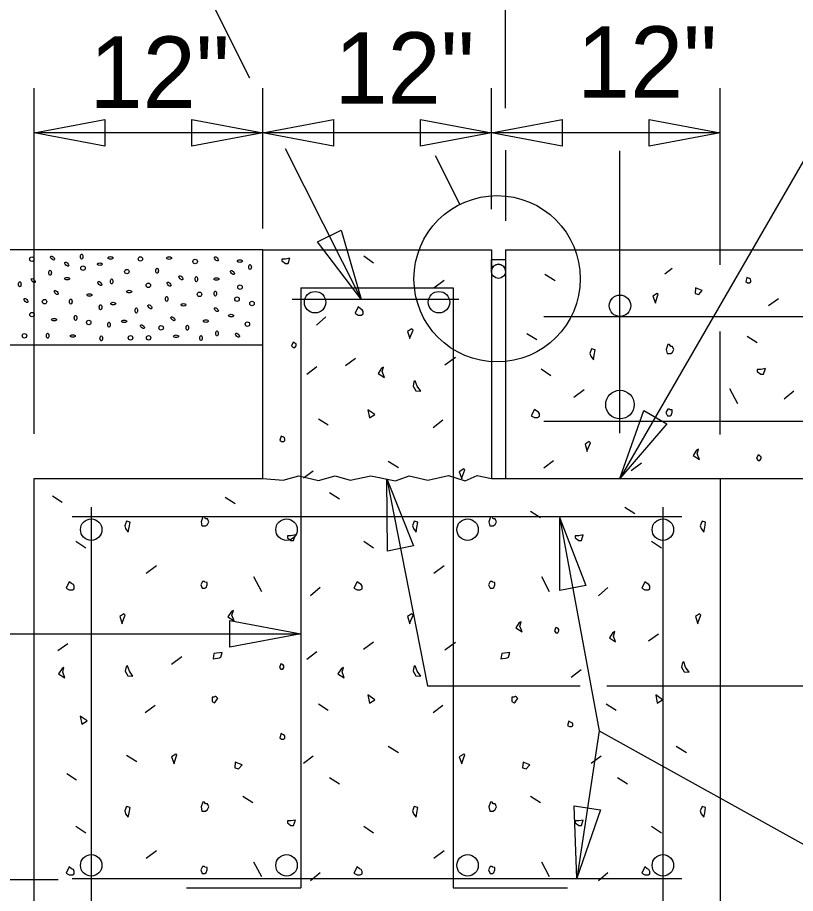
# Model space of a CAD drawing. Extents: x 0 to 68.6, y 0 to 47.1.
# Drawn here: x 29.508 to 32.911, y 9.542 to 13.374 of the extents above; entities that cross this region are included whole.
import ezdxf

# ---------------------------------------------------------------- set-up
doc = ezdxf.new("R2010")
doc.units = 0
for name, color, linetype in [('BRDG_ANNO_General-Notes', 7, 'Continuous'), ('BRDG_BASE_Dtlctrln', 7, 'Continuous'), ('BRDG_BASE_Obj-Line', 7, 'Continuous'), ('BRDG_BASE_Pattern', 7, 'Continuous'), ('BRDG_BASE_Phtline', 7, 'Continuous'), ('BRDG_BASE_Rebar', 7, 'Continuous')]:
    doc.layers.add(name, color=color, linetype=linetype)

msp = doc.modelspace()

# ---------------------------------------------------------------- linework, layer by layer
at = {"layer": 'BRDG_ANNO_General-Notes'}
for p, q in [((31.6432, 12.9771), (31.6432, 16.4234)), ((33.6072, 13.8941), (32.1432, 11.3574)), ((30.3453, 13.4631), (30.5235, 13.1091)), ((29.5807, 11.5523), (29.5807, 13.0643)), ((30.5807, 12.4506), (30.5807, 13.0643)), ((31.5807, 12.5345), (31.5807, 13.0643)), ((32.5807, 12.2915), (32.5807, 13.0643)), ((29.5807, 12.8689), (29.8907, 12.927)), ((29.8907, 12.927), (29.8907, 12.8107)), ((30.2707, 12.8107), (30.2707, 12.927)), ((30.2707, 12.927), (30.5807, 12.8689)), ((30.5807, 12.8689), (30.8907, 12.927)), ((30.8907, 12.927), (30.8907, 12.8107)), ((31.2707, 12.8107), (31.2707, 12.927)), ((31.2707, 12.927), (31.5807, 12.8689)), ((31.5807, 12.8689), (31.8907, 12.927)), ((31.8907, 12.927), (31.8907, 12.8107)), ((32.2707, 12.8107), (32.2707, 12.927)), ((32.2707, 12.927), (32.5807, 12.8689)), ((30.5807, 12.8689), (29.5807, 12.8689)), ((29.8907, 12.8107), (29.5807, 12.8689)), ((30.5807, 12.8689), (30.2707, 12.8107)), ((31.5807, 12.8689), (30.5807, 12.8689)), ((30.8907, 12.8107), (30.5807, 12.8689)), ((31.5807, 12.8689), (31.2707, 12.8107)), ((32.5807, 12.8689), (31.5807, 12.8689)), ((31.8907, 12.8107), (31.5807, 12.8689)), ((32.5807, 12.8689), (32.2707, 12.8107)), ((30.6793, 12.7999), (31.0113, 12.1409)), ((31.3344, 12.7696), (31.4423, 12.5557)), ((31.6432, 12.7928), (31.6432, 12.4835)), ((30.8199, 12.3916), (30.9237, 12.4439)), ((30.9237, 12.4439), (31.0113, 12.1409)), ((31.0113, 12.1409), (30.8199, 12.3916)), ((32.5807, 11.5499), (32.5807, 11.9998)), ((32.1432, 11.3574), (32.2479, 11.6549)), ((32.2479, 11.6549), (32.3485, 11.5968)), ((32.3485, 11.5968), (32.1432, 11.3574)), ((31.1243, 11.3549), (31.3008, 10.45)), ((31.1266, 11.0395), (31.1243, 11.3549)), ((31.1243, 11.3549), (31.2407, 11.0618)), ((31.8792, 11.1907), (32.0517, 10.2532)), ((31.8795, 10.8678), (31.8806, 11.1832)), ((31.8806, 11.1832), (31.9939, 10.8888)), ((31.2407, 11.0618), (31.1266, 11.0395)), ((31.9939, 10.8888), (31.8795, 10.8678)), ((30.4374, 10.6197), (30.4374, 10.7359)), ((30.4374, 10.7359), (30.7474, 10.6778)), ((27.2469, 10.6778), (30.7474, 10.6778)), ((30.7474, 10.6778), (30.4374, 10.6197)), ((31.3008, 10.45), (31.9689, 10.45)), ((32.0853, 10.45), (36.1729, 10.45)), ((32.0517, 10.2532), (31.9548, 9.6074)), ((32.0517, 10.2532), (34.1182, 9.106)), ((31.9436, 9.9245), (32.0586, 9.9073)), ((31.9552, 9.6093), (31.9436, 9.9245)), ((32.0586, 9.9073), (31.9552, 9.6093)), ((29.6858, 9.6015), (28.1252, 9.6015))]:
    msp.add_line(p, q, dxfattribs=at)
msp.add_circle((31.6059, 12.2307), 0.3638, dxfattribs=at)
at = {"layer": 'BRDG_BASE_Dtlctrln'}
for p, q in [((32.1432, 11.5559), (32.1432, 12.7897)), ((30.7101, 12.1409), (31.439, 12.1409)), ((29.8307, 11.2319), (29.8307, 8.9946)), ((32.3307, 11.2319), (32.3307, 8.5728))]:
    msp.add_line(p, q, dxfattribs=at)
at = {"layer": 'BRDG_BASE_Obj-Line'}
for p, q in [((30.5807, 12.3574), (31.5807, 12.3574)), ((30.5807, 11.3574), (30.5807, 12.3574)), ((31.5807, 12.3574), (31.5807, 11.3574)), ((31.6432, 12.3574), (31.6432, 11.3574)), ((31.6432, 12.3574), (36.621, 12.3574)), ((29.5807, 9.3574), (29.5807, 11.3574)), ((29.5807, 11.3574), (30.5807, 11.3574)), ((31.5807, 11.3574), (32.5807, 11.3574)), ((31.6432, 11.3574), (36.621, 11.3574)), ((32.5807, 11.3574), (32.5807, 9.3574))]:
    msp.add_line(p, q, dxfattribs=at)
msp.add_lwpolyline([(30.5807, 11.3574), (30.6703, 11.35), (30.7392, 11.3685), (30.8254, 11.3482), (30.8983, 11.3685), (30.9631, 11.35), (31.0534, 11.3685), (31.1608, 11.3463), (31.2215, 11.3685), (31.3027, 11.35), (31.3938, 11.3703), (31.4667, 11.3463), (31.5184, 11.3703), (31.5807, 11.3574)], dxfattribs=at)
at = {"layer": 'BRDG_BASE_Pattern'}
for p, q in [((31.0226, 12.3306), (31.0658, 12.301)), ((32.3718, 12.2763), (32.3388, 12.2515)), ((31.8142, 12.2503), (31.8595, 12.2229)), ((31.3742, 12.2229), (31.3295, 12.1895)), ((32.836, 12.1435), (32.7928, 12.112)), ((30.8575, 12.064), (30.8154, 12.0285)), ((31.7357, 11.992), (31.779, 11.9645)), ((32.7001, 11.979), (32.7436, 11.9513)), ((30.9865, 11.8817), (30.943, 11.8503)), ((31.4234, 11.887), (31.3775, 11.8528)), ((30.8177, 11.8456), (30.7744, 11.8122)), ((31.7981, 11.8372), (31.8414, 11.8077)), ((31.986, 11.7455), (31.9415, 11.712)), ((32.6225, 11.7503), (32.6566, 11.6853)), ((32.9033, 11.7396), (32.8614, 11.7041)), ((30.8243, 11.6186), (30.8675, 11.5911)), ((31.3689, 11.6115), (31.3256, 11.5786)), ((31.13, 11.4328), (31.1753, 11.4054)), ((31.8532, 11.4339), (31.8099, 11.4025)), ((32.2375, 11.4244), (32.1916, 11.3902)), ((30.8019, 11.3896), (30.7586, 11.3582)), ((29.661, 11.2811), (29.7043, 11.2534)), ((30.417, 11.2758), (30.4603, 11.2483)), ((30.8735, 11.2965), (30.9168, 11.2688)), ((32.1647, 11.2312), (32.208, 11.2038)), ((31.7521, 11.2145), (31.7954, 11.1868)), ((29.764, 11.0832), (29.8072, 11.0537)), ((31.0226, 11.0832), (31.0658, 11.0537)), ((32.2809, 11.0832), (32.3242, 11.0537)), ((30.1156, 10.9756), (30.0711, 10.9421)), ((31.3742, 10.9756), (31.3295, 10.9421)), ((30.5409, 10.9276), (30.5749, 10.8628)), ((31.7993, 10.9276), (31.8335, 10.8628)), ((30.8323, 10.8798), (30.7902, 10.8444)), ((32.0907, 10.8798), (32.0486, 10.8444)), ((32.3115, 10.6766), (32.2682, 10.6452)), ((29.7279, 10.6344), (29.6846, 10.6028)), ((31.065, 10.6405), (31.0217, 10.609)), ((31.4234, 10.6397), (31.3775, 10.6055)), ((30.2271, 10.5774), (30.1812, 10.5431)), ((30.8177, 10.5983), (30.7744, 10.5648)), ((31.9734, 10.5197), (31.9301, 10.4864)), ((30.1105, 10.3641), (30.067, 10.3313)), ((30.8243, 10.3713), (30.8675, 10.3436)), ((31.3689, 10.3641), (31.3256, 10.3313)), ((32.0829, 10.3713), (32.1261, 10.3436)), ((31.13, 10.1855), (31.1753, 10.158)), ((32.3886, 10.1855), (32.4339, 10.158)), ((29.9848, 10.1464), (30.0301, 10.1189)), ((30.8019, 10.1422), (30.7586, 10.1107)), ((32.0605, 10.1422), (32.0172, 10.1107)), ((29.7237, 10.0672), (29.767, 10.0395)), ((30.8735, 10.0492), (30.9168, 10.0215)), ((32.1321, 10.0492), (32.1754, 10.0215)), ((30.4935, 9.9671), (30.537, 9.9395)), ((31.7521, 9.9671), (31.7954, 9.9395)), ((29.764, 9.8359), (29.8072, 9.8064)), ((31.0226, 9.8359), (31.0658, 9.8064)), ((32.2809, 9.8359), (32.3242, 9.8064)), ((30.1156, 9.7282), (30.0711, 9.6948)), ((31.3742, 9.7282), (31.3295, 9.6948)), ((30.5409, 9.6803), (30.5749, 9.6153)), ((31.7993, 9.6803), (31.8335, 9.6153)), ((30.8323, 9.6325), (30.7902, 9.597)), ((32.0907, 9.6325), (32.0486, 9.597))]:
    msp.add_line(p, q, dxfattribs=at)
for points in [[(30.6801, 12.317), (30.6643, 12.317), (30.6643, 12.3093), (30.6801, 12.2973), (30.692, 12.2973), (30.6998, 12.3211)], [(32.6984, 12.2366), (32.6933, 12.2181), (32.7011, 12.2128), (32.7104, 12.2128), (32.7157, 12.2169), (32.7157, 12.2234), (32.7142, 12.2286), (32.7091, 12.2312)], [(32.4737, 12.1913), (32.4718, 12.1663), (32.4876, 12.1624), (32.5032, 12.1794)], [(32.2864, 12.155), (32.2983, 12.1236), (32.2983, 12.1276), (32.3102, 12.163), (32.306, 12.1669)], [(30.9987, 12.1073), (30.985, 12.0796), (30.9987, 12.0718), (31.0125, 12.0718), (31.0203, 12.0771), (31.0203, 12.0876), (31.0164, 12.0954), (31.0086, 12.0993)], [(31.2147, 12.0004), (31.2245, 11.9691), (31.2245, 11.973), (31.2383, 12.0064), (31.2325, 12.0123)], [(30.7133, 11.9533), (30.7068, 11.9375), (30.7133, 11.9297), (30.7214, 11.9297), (30.7265, 11.9375), (30.7265, 11.9455), (30.7252, 11.9455), (30.7214, 11.9494)], [(32.0191, 11.9238), (32.0113, 11.9041), (32.0152, 11.8922), (32.0271, 11.8766), (32.031, 11.8963), (32.0349, 11.9198)], [(32.3453, 11.9217), (32.3493, 11.9034), (32.357, 11.9034), (32.365, 11.9034), (32.3728, 11.91), (32.3794, 11.9217), (32.3728, 11.9348), (32.365, 11.9348), (32.3597, 11.9428), (32.3531, 11.9428)], [(31.1009, 11.8403), (31.0851, 11.8167), (31.1128, 11.7989), (31.1035, 11.8245), (31.1086, 11.8442)], [(32.7596, 11.8337), (32.7438, 11.8337), (32.7438, 11.8257), (32.7596, 11.8141), (32.7713, 11.8141), (32.7793, 11.8376)], [(31.2424, 11.7806), (31.2383, 11.7609), (31.2502, 11.7412), (31.2719, 11.7394), (31.2561, 11.7609), (31.2481, 11.7847)], [(31.0408, 11.6574), (31.0473, 11.6219), (31.0709, 11.6363)], [(31.7692, 11.6592), (31.7554, 11.6318), (31.7692, 11.624), (31.7829, 11.624), (31.7909, 11.6291), (31.7909, 11.6395), (31.787, 11.6476), (31.779, 11.6515)], [(32.3439, 11.6461), (32.3505, 11.6305), (32.3558, 11.6305), (32.3623, 11.6305), (32.3677, 11.6344), (32.3716, 11.6461), (32.3716, 11.6568), (32.3623, 11.658), (32.3597, 11.6607), (32.3519, 11.6607)], [(30.6608, 11.5426), (30.6557, 11.5241), (30.6635, 11.519), (30.6727, 11.519), (30.6781, 11.5229), (30.6781, 11.5294), (30.6766, 11.5345), (30.6715, 11.5372)], [(31.9904, 11.5071), (32.0002, 11.4755), (32.0002, 11.4796), (32.014, 11.513), (32.008, 11.519)], [(32.4784, 11.4808), (32.4628, 11.4572), (32.4903, 11.4402), (32.4805, 11.4651), (32.4864, 11.4847)], [(32.7474, 11.4599), (32.7409, 11.4441), (32.7474, 11.4361), (32.7554, 11.4361), (32.7606, 11.4441), (32.7606, 11.4519), (32.7594, 11.4519), (32.7554, 11.4558)], [(31.4404, 11.3869), (31.4523, 11.3555), (31.4523, 11.3594), (31.464, 11.3949), (31.4601, 11.3988)], [(29.985, 11.1698), (29.9772, 11.1501), (29.9811, 11.1384), (29.993, 11.1226), (29.9969, 11.1423), (30.0008, 11.1659)], [(30.3112, 11.1679), (30.3151, 11.1495), (30.3229, 11.1495), (30.3309, 11.1495), (30.3387, 11.156), (30.3453, 11.1679), (30.3387, 11.181), (30.3309, 11.181), (30.3256, 11.1889), (30.319, 11.1889)], [(31.2436, 11.1698), (31.2358, 11.1501), (31.2397, 11.1384), (31.2514, 11.1226), (31.2555, 11.1423), (31.2594, 11.1659)], [(31.5696, 11.1679), (31.5738, 11.1495), (31.5815, 11.1495), (31.5893, 11.1495), (31.5973, 11.156), (31.6039, 11.1679), (31.5973, 11.181), (31.5893, 11.181), (31.5842, 11.1889), (31.5776, 11.1889)], [(32.5022, 11.1698), (32.4942, 11.1501), (32.4981, 11.1384), (32.51, 11.1226), (32.5139, 11.1423), (32.5178, 11.1659)], [(30.7043, 11.1062), (30.6885, 11.1062), (30.6885, 11.0982), (30.7043, 11.0865), (30.716, 11.0865), (30.724, 11.1101)], [(31.9627, 11.1062), (31.9469, 11.1062), (31.9469, 11.0982), (31.9627, 11.0865), (31.9746, 11.0865), (31.9824, 11.1101)], [(29.735, 10.9055), (29.7213, 10.8778), (29.735, 10.87), (29.7487, 10.87), (29.7568, 10.8751), (29.7568, 10.8858), (29.7529, 10.8935), (29.7449, 10.8974)], [(30.3098, 10.8923), (30.3164, 10.8766), (30.3217, 10.8766), (30.3282, 10.8766), (30.3335, 10.8804), (30.3375, 10.8923), (30.3375, 10.9028), (30.3282, 10.904), (30.3256, 10.9067), (30.3178, 10.9067)], [(30.9936, 10.9055), (30.9799, 10.8778), (30.9936, 10.87), (31.0074, 10.87), (31.0152, 10.8751), (31.0152, 10.8858), (31.0113, 10.8935), (31.0035, 10.8974)], [(31.5684, 10.8923), (31.5749, 10.8766), (31.5803, 10.8766), (31.5869, 10.8766), (31.592, 10.8804), (31.5959, 10.8923), (31.5959, 10.9028), (31.5869, 10.904), (31.5842, 10.9067), (31.5762, 10.9067)], [(32.252, 10.9055), (32.2383, 10.8778), (32.252, 10.87), (32.266, 10.87), (32.2737, 10.8751), (32.2737, 10.8858), (32.2699, 10.8935), (32.2619, 10.8974)], [(30.4443, 10.7753), (30.4287, 10.7517), (30.4562, 10.7346), (30.4464, 10.7595), (30.4523, 10.7792)], [(29.9563, 10.7531), (29.9661, 10.7217), (29.9661, 10.7256), (29.9798, 10.7591), (29.9739, 10.765)], [(31.2147, 10.7531), (31.2245, 10.7217), (31.2245, 10.7256), (31.2383, 10.7591), (31.2325, 10.765)], [(31.7029, 10.7269), (31.6871, 10.7033), (31.7148, 10.6862), (31.7049, 10.711), (31.7107, 10.7307)], [(32.4733, 10.7531), (32.4831, 10.7217), (32.4831, 10.7256), (32.4969, 10.7591), (32.4909, 10.765)], [(31.8633, 10.7059), (31.8567, 10.6902), (31.8633, 10.6823), (31.871, 10.6823), (31.8764, 10.6902), (31.8764, 10.6979), (31.8749, 10.6979), (31.871, 10.702)], [(32.1126, 10.6834), (32.0968, 10.6598), (32.1243, 10.6422), (32.1151, 10.6676), (32.1204, 10.6873)], [(30.3676, 10.5911), (30.3637, 10.5675), (30.3912, 10.5727), (30.3978, 10.5759), (30.4031, 10.5962)], [(31.6262, 10.5911), (31.6221, 10.5675), (31.6498, 10.5727), (31.6564, 10.5759), (31.6615, 10.5962)], [(30.6602, 10.5466), (30.6536, 10.5308), (30.6602, 10.523), (30.6682, 10.523), (30.6733, 10.5308), (30.6733, 10.5386), (30.6721, 10.5386), (30.6682, 10.5427)], [(32.4161, 10.5514), (32.4122, 10.5317), (32.4241, 10.512), (32.4456, 10.5101), (32.43, 10.5317), (32.422, 10.5552)], [(29.9838, 10.5333), (29.9798, 10.5136), (29.9916, 10.4939), (30.0133, 10.4921), (29.9975, 10.5136), (29.9897, 10.5372)], [(30.9258, 10.5265), (30.91, 10.5027), (30.9374, 10.4851), (30.9282, 10.5107), (30.9335, 10.5304)], [(31.2424, 10.5333), (31.2383, 10.5136), (31.2502, 10.4939), (31.2719, 10.4921), (31.2561, 10.5136), (31.2481, 10.5372)], [(30.3594, 10.4008), (30.3594, 10.3811), (30.3693, 10.3752), (30.3731, 10.3791), (30.3791, 10.3871), (30.3848, 10.3949), (30.3791, 10.4008), (30.375, 10.4027), (30.3731, 10.4027), (30.3672, 10.4008)], [(31.0408, 10.4101), (31.0473, 10.3746), (31.0709, 10.3889)], [(31.6707, 10.4008), (31.6707, 10.3811), (31.6806, 10.3752), (31.6845, 10.3791), (31.6904, 10.3871), (31.6964, 10.3949), (31.6904, 10.4008), (31.6865, 10.4027), (31.6845, 10.4027), (31.6787, 10.4008)], [(32.2994, 10.4101), (32.306, 10.3746), (32.3296, 10.3889)], [(29.7824, 10.3178), (29.789, 10.2823), (29.8126, 10.2967)], [(31.9195, 10.2952), (31.9141, 10.2768), (31.9221, 10.2715), (31.9314, 10.2715), (31.9365, 10.2755), (31.9365, 10.2821), (31.9352, 10.2872), (31.9299, 10.2899)], [(30.6608, 10.2411), (30.6557, 10.2226), (30.6635, 10.2173), (30.6727, 10.2173), (30.6781, 10.2214), (30.6781, 10.228), (30.6766, 10.2331), (30.6715, 10.2357)], [(30.1818, 10.1396), (30.1937, 10.1082), (30.1937, 10.1121), (30.2056, 10.1476), (30.2015, 10.1515)], [(31.4404, 10.1396), (31.4523, 10.1082), (31.4523, 10.1121), (31.464, 10.1476), (31.4601, 10.1515)], [(30.4607, 10.116), (30.4589, 10.091), (30.4746, 10.0871), (30.4902, 10.1041)], [(31.7193, 10.116), (31.7173, 10.091), (31.7331, 10.0871), (31.7489, 10.1041)], [(30.3112, 9.9204), (30.3151, 9.9021), (30.3229, 9.9021), (30.3309, 9.9021), (30.3387, 9.9087), (30.3453, 9.9204), (30.3387, 9.9335), (30.3309, 9.9335), (30.3256, 9.9415), (30.319, 9.9415)], [(31.5696, 9.9204), (31.5738, 9.9021), (31.5815, 9.9021), (31.5893, 9.9021), (31.5973, 9.9087), (31.6039, 9.9204), (31.5973, 9.9335), (31.5893, 9.9335), (31.5842, 9.9415), (31.5776, 9.9415)], [(29.985, 9.9224), (29.9772, 9.9028), (29.9811, 9.8908), (29.993, 9.8753), (29.9969, 9.8949), (30.0008, 9.9185)], [(31.2436, 9.9224), (31.2358, 9.9028), (31.2397, 9.8908), (31.2514, 9.8753), (31.2555, 9.8949), (31.2594, 9.9185)], [(32.5022, 9.9224), (32.4942, 9.9028), (32.4981, 9.8908), (32.51, 9.8753), (32.5139, 9.8949), (32.5178, 9.9185)], [(30.7043, 9.8589), (30.6885, 9.8589), (30.6885, 9.8508), (30.7043, 9.8392), (30.716, 9.8392), (30.724, 9.8628)], [(31.9627, 9.8589), (31.9469, 9.8589), (31.9469, 9.8508), (31.9627, 9.8392), (31.9746, 9.8392), (31.9824, 9.8628)], [(29.735, 9.6579), (29.7213, 9.6304), (29.735, 9.6227), (29.7487, 9.6227), (29.7568, 9.6278), (29.7568, 9.6382), (29.7529, 9.6463), (29.7449, 9.6501)], [(30.3098, 9.6448), (30.3164, 9.6292), (30.3217, 9.6292), (30.3282, 9.6292), (30.3335, 9.6331), (30.3375, 9.6448), (30.3375, 9.6555), (30.3282, 9.6567), (30.3256, 9.6594), (30.3178, 9.6594)], [(30.9936, 9.6579), (30.9799, 9.6304), (30.9936, 9.6227), (31.0074, 9.6227), (31.0152, 9.6278), (31.0152, 9.6382), (31.0113, 9.6463), (31.0035, 9.6501)], [(31.5684, 9.6448), (31.5749, 9.6292), (31.5803, 9.6292), (31.5869, 9.6292), (31.592, 9.6331), (31.5959, 9.6448), (31.5959, 9.6555), (31.5869, 9.6567), (31.5842, 9.6594), (31.5762, 9.6594)], [(32.252, 9.6579), (32.2383, 9.6304), (32.252, 9.6227), (32.266, 9.6227), (32.2737, 9.6278), (32.2737, 9.6382), (32.2699, 9.6463), (32.2619, 9.6501)]]:
    msp.add_lwpolyline(points, close=True, dxfattribs=at)
for points in [[(30.1933, 11.3568), (30.1937, 11.3555), (30.1937, 11.3568)], [(29.6877, 10.5027), (29.7151, 10.4849), (29.7061, 10.5105), (29.7112, 10.5302), (29.7034, 10.5263), (29.6877, 10.5027)]]:
    msp.add_lwpolyline(points, dxfattribs=at)
at = {"layer": 'BRDG_BASE_Phtline'}
for p, q in [((30.5807, 12.3574), (28.3307, 12.3574)), ((31.5807, 12.2636), (31.5807, 12.3157)), ((31.5807, 12.3157), (31.6432, 12.3157)), ((31.6432, 12.3157), (31.6432, 12.2636)), ((30.5807, 11.9407), (28.3307, 11.9407))]:
    msp.add_line(p, q, dxfattribs=at)
for centre in [(29.5709, 12.3167), (30.0459, 12.3176), (30.2851, 12.3064), (29.7946, 12.277), (29.9867, 12.2622), (30.0806, 12.2022), (30.4815, 12.1941), (30.3043, 12.1625), (30.4681, 12.1417), (29.6267, 12.1305), (30.534, 12.1227), (29.5719, 12.0741), (29.82, 12.0396), (30.5139, 12.0321), (30.1365, 12.0159), (29.5388, 11.9814), (30.0028, 11.9724), (30.0817, 11.9726)]:
    msp.add_circle(centre, 0.00976, dxfattribs=at)
msp.add_arc((31.612, 12.2636), 0.0312, 0, 180, dxfattribs=at)
for centre, major_axis in [((29.7887, 12.3279), (0, -0.011)), ((29.6613, 12.3215), (0.00779, -0.00779)), ((29.7236, 12.2947), (0.00779, -0.00779)), ((29.9152, 12.3222), (-0.011, 0)), ((30.1714, 12.3212), (-0.011, 0)), ((30.3781, 12.318), (0.00779, -0.00779)), ((30.4809, 12.3079), (-0.011, 0)), ((29.6511, 12.2569), (0, -0.011)), ((29.8685, 12.2946), (-0.011, 0)), ((30.119, 12.2658), (0, -0.011)), ((30.4485, 12.2581), (0.00779, -0.00779)), ((30.5256, 12.2818), (0, -0.011)), ((29.5775, 12.2227), (0.00779, -0.00779)), ((29.725, 12.2312), (-0.011, 0)), ((29.9201, 12.2189), (0, -0.011)), ((30.2229, 12.235), (0.00779, -0.00779)), ((30.2907, 12.229), (0, -0.011)), ((30.3782, 12.2297), (-0.011, 0)), ((29.5185, 12.2065), (0, -0.011)), ((29.8683, 12.2101), (0.00779, -0.00779)), ((30.1711, 12.207), (0.00779, -0.00779)), ((29.678, 12.1705), (0.00779, -0.00779)), ((29.8227, 12.16), (-0.011, 0)), ((29.9967, 12.1748), (-0.011, 0)), ((30.1609, 12.1424), (0, -0.011)), ((30.3738, 12.1662), (0, -0.011)), ((29.5452, 12.1358), (0.00779, -0.00779)), ((29.7415, 12.131), (0, 0.011)), ((29.8714, 12.1062), (0, -0.011)), ((29.9269, 12.1223), (-0.011, 0)), ((30.0873, 12.1082), (0.00779, -0.00779)), ((30.2348, 12.1167), (-0.011, 0)), ((29.7621, 12.0597), (0, -0.011)), ((30.0282, 12.092), (0, -0.011)), ((30.378, 12.0956), (0.00779, -0.00779)), ((30.4425, 12.0698), (-0.011, 0)), ((29.6684, 12.0521), (-0.011, 0)), ((29.9085, 12.0297), (0, -0.011)), ((29.9748, 12.0447), (-0.011, 0)), ((30.1878, 12.056), (0.00779, -0.00779)), ((30.3324, 12.0455), (-0.011, 0)), ((30.0549, 12.0212), (0.00779, -0.00779)), ((30.2512, 12.0164), (0, 0.011)), ((30.3811, 11.9917), (0, -0.011)), ((29.6401, 11.9814), (0, -0.011)), ((29.7501, 11.9807), (-0.011, 0)), ((29.8745, 11.9701), (0, -0.011)), ((30.2016, 11.9794), (-0.011, 0)), ((30.3109, 11.9712), (0, -0.011)), ((30.4704, 11.9839), (0.00779, -0.00779))]:
    msp.add_ellipse(centre, major_axis=major_axis, ratio=0.5, dxfattribs=at)
at = {"layer": 'BRDG_BASE_Rebar'}
for p, q in [((30.7474, 12.1907), (31.4141, 12.1907)), ((30.7474, 12.1907), (30.7474, 9.5657)), ((31.4141, 12.1907), (31.4141, 9.5657)), ((31.8099, 12.0657), (36.6113, 12.0657)), ((31.8099, 11.6074), (36.6113, 11.6074)), ((29.7474, 11.1907), (32.4141, 11.1907)), ((29.7474, 9.6074), (32.4141, 9.6074)), ((30.2474, 9.5657), (30.7474, 9.5657)), ((31.4141, 9.5657), (31.9141, 9.5657))]:
    msp.add_line(p, q, dxfattribs=at)
for centre, radius in [((31.612, 12.2636), 0.0312), ((30.8099, 12.1282), 0.0469), ((31.3516, 12.1282), 0.0469), ((32.1432, 12.1126), 0.0469), ((32.1432, 11.6803), 0.0625), ((29.8307, 11.1334), 0.0469), ((30.6849, 11.1334), 0.0469), ((31.4766, 11.1334), 0.0469), ((32.3307, 11.1334), 0.0469), ((29.8307, 9.6647), 0.0469), ((30.6849, 9.6647), 0.0469), ((31.4766, 9.6647), 0.0469), ((32.3307, 9.6647), 0.0469)]:
    msp.add_circle(centre, radius, dxfattribs=at)

# ---------------------------------------------------------------- texts
at = {"layer": 'BRDG_ANNO_General-Notes'}
for p in [(31.955, 13.0226), (30.8944, 12.9966), (29.8233, 12.9783)]:
    msp.add_text('12"', height=0.3125, dxfattribs=at).set_placement(p)

doc.saveas('drawing.dxf')
